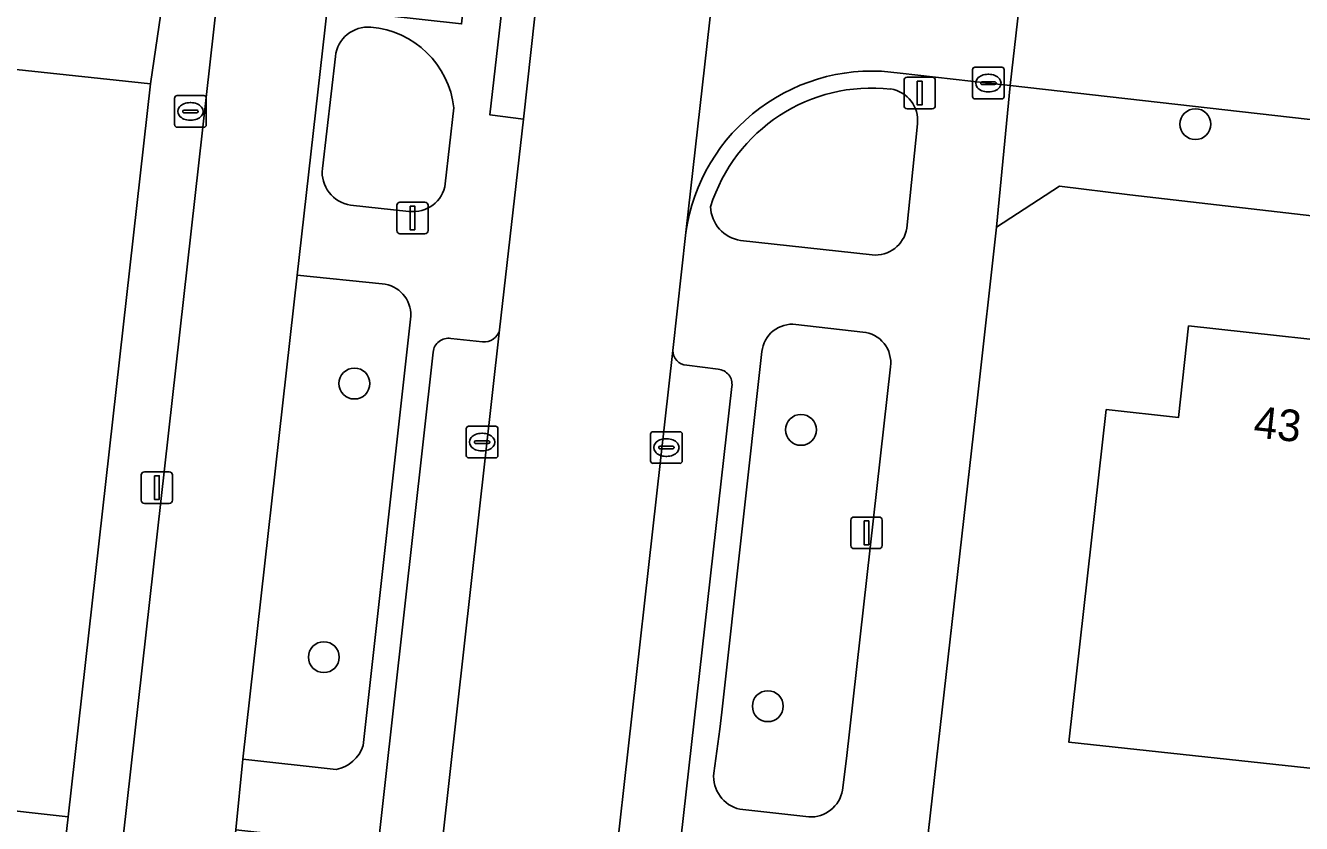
# Model space of a CAD drawing. Extents: x 162026 to 163502, y 387295 to 388169.
# Drawn here: x 162271.99 to 162312.4, y 387792.48 to 387817.74 of the extents above; entities that cross this region are included whole.
import ezdxf

# ---------------------------------------------------------------- set-up
doc = ezdxf.new("R2010")
doc.units = 0
for name, color, linetype in [('IMGEO_Berm_groen', 7, 'Continuous'), ('IMGEO_Boom', 7, 'Continuous'), ('IMGEO_Brandkraan', 7, 'Continuous'), ('IMGEO_Erf', 7, 'Continuous'), ('IMGEO_Fietspad_gesloten', 7, 'Continuous'), ('IMGEO_Groenvoorziening', 7, 'Continuous'), ('IMGEO_Kolk', 7, 'Continuous'), ('IMGEO_Lichtmast', 7, 'Continuous'), ('IMGEO_Muur', 7, 'Continuous'), ('IMGEO_Pand', 7, 'Continuous'), ('IMGEO_Pand_nummerreeks', 7, 'Continuous'), ('IMGEO_Parkeervlak_open', 7, 'Continuous'), ('IMGEO_Rijbaan_lokaal_gesloten', 7, 'Continuous'), ('IMGEO_Rijbaan_lokaal_open', 7, 'Continuous'), ('IMGEO_Voetpad_open', 7, 'Continuous')]:
    doc.layers.add(name, color=color, linetype=linetype)

msp = doc.modelspace()

# ---------------------------------------------------------------- linework, layer by layer
at = {"layer": 'IMGEO_Berm_groen'}
for points in [[(162283.29, 387809.569), (162280.59, 387809.842), (162278.879, 387794.52), (162281.83, 387794.192)], [(162282.682, 387794.949), (162284.192, 387808.546)]]:
    msp.add_lwpolyline(points, dxfattribs=at)
for centre, radius, start, end in [((162283.197, 387808.578), 0.995, 358.159, 84.6476), ((162281.627, 387795.278), 1.105, 280.573, 342.669)]:
    msp.add_arc(centre, radius, start, end, dxfattribs=at)
at = {"layer": 'IMGEO_Boom'}
for centre in [(162309.038, 387814.62), (162282.408, 387806.409), (162296.549, 387804.942), (162281.44, 387797.746), (162295.498, 387796.193)]:
    msp.add_circle(centre, 0.489, dxfattribs=at)
at = {"layer": 'IMGEO_Brandkraan'}
for p, q in [((162276.715, 387814.598), (162276.715, 387815.45)), ((162276.79, 387815.524), (162277.642, 387815.524)), ((162277.203, 387815.304), (162277.228, 387815.304)), ((162277.716, 387815.45), (162277.716, 387814.598)), ((162276.974, 387815.018), (162276.974, 387815.03)), ((162277.412, 387814.981), (162277.014, 387814.981)), ((162277.017, 387815.067), (162277.415, 387815.067)), ((162277.458, 387815.03), (162277.458, 387815.018)), ((162277.642, 387814.524), (162276.79, 387814.524)), ((162277.226, 387814.744), (162277.201, 387814.744))]:
    msp.add_line(p, q, dxfattribs=at)
for points in [[(162276.715, 387814.598), (162276.715, 387815.45)], [(162276.79, 387815.524), (162277.642, 387815.524)], [(162277.716, 387815.45), (162277.716, 387814.598)], [(162277.642, 387814.524), (162276.79, 387814.524)]]:
    msp.add_lwpolyline(points, dxfattribs=at)
for centre, radius, start, end in [((162276.792, 387815.448), 0.0765, 91.552, 178.448), ((162276.792, 387815.448), 0.0765, 91.552, 178.448), ((162277.64, 387815.448), 0.0765, 1.552, 88.448), ((162277.64, 387815.448), 0.0765, 1.552, 88.448), ((162277.014, 387815.027), 0.0403, 85.8775, 175.7526), ((162277.011, 387815.017), 0.0366, 178.938, 274.7102), ((162277.415, 387815.024), 0.043, 264.8664, 352.4533), ((162277.419, 387815.029), 0.0386, 1.7309, 96.639), ((162276.792, 387814.6), 0.0765, 181.552, 268.448), ((162276.792, 387814.6), 0.0765, 181.552, 268.448), ((162277.64, 387814.6), 0.0765, 271.552, 358.448), ((162277.64, 387814.6), 0.0765, 271.552, 358.448)]:
    msp.add_arc(centre, radius, start, end, dxfattribs=at)
for centre, major_axis, ratio, start_param, end_param in [((162277.202, 387815.024), (-0.387, 0.002), 0.722429, 4.712389, 7.853982), ((162277.227, 387815.024), (-0.39, 0.002), 0.717154, 1.570796, 4.712389)]:
    msp.add_ellipse(centre, major_axis=major_axis, ratio=ratio, start_param=start_param, end_param=end_param, dxfattribs=at)
at = {"layer": 'IMGEO_Erf'}
for points in [[(162275.948, 387815.9), (162270.899, 387816.432), (162239.75, 387819.947)], [(162230.846, 387799.89), (162235.219, 387799.415), (162234.953, 387796.965), (162242.578, 387796.117), (162273.341, 387792.696), (162275.948, 387815.9)], [(162360.929, 387806.153), (162306.963, 387812.388), (162304.731, 387812.656), (162302.745, 387811.357), (162302.135, 387805.96), (162300.281, 387789.552), (162306.672, 387788.828), (162307.029, 387791.981), (162313.859, 387791.208)], [(162314.036, 387794.079), (162305.036, 387795.05), (162306.214, 387805.585), (162308.506, 387805.337), (162308.825, 387808.234), (162315.35, 387807.516)]]:
    msp.add_lwpolyline(points, dxfattribs=at)
at = {"layer": 'IMGEO_Fietspad_gesloten'}
for points in [[(162288.097, 387908.488), (162278.956, 387826.545), (162278.87, 387825.665), (162278.372, 387825.72), (162277.589, 387818.699), (162278.067, 387818.669), (162270.183, 387748.502), (162261.381, 387669.505)], [(162272.106, 387733.912), (162275.454, 387763.658), (162275.701, 387765.902), (162278.652, 387792.276), (162278.879, 387794.52), (162280.59, 387809.842), (162281.546, 387818.246), (162282.058, 387818.211), (162282.843, 387825.189), (162282.325, 387825.242), (162283.687, 387837.34), (162286.582, 387863.057), (162286.832, 387865.282)]]:
    msp.add_lwpolyline(points, dxfattribs=at)
at = {"layer": 'IMGEO_Groenvoorziening'}
for points in [[(162281.805, 387816.766), (162281.392, 387813.219)], [(162285.286, 387812.735), (162285.557, 387815.137)], [(162299.898, 387811.328), (162300.234, 387814.631)], [(162282.288, 387812.06), (162284.135, 387811.861)], [(162294.631, 387810.939), (162298.798, 387810.481)], [(162298.505, 387808.039), (162296.389, 387808.281)], [(162295.313, 387807.419), (162294.044, 387796.005), (162293.984, 387795.465), (162293.785, 387794.073)], [(162297.868, 387793.536), (162297.989, 387794.536), (162299.382, 387806.943)], [(162294.612, 387792.931), (162296.796, 387792.686)]]:
    msp.add_lwpolyline(points, dxfattribs=at)
for centre, radius, start, end in [((162282.835, 387816.659), 1.035, 84.6226, 174.0724), ((162282.689, 387814.814), 2.886, 6.4231, 85.1702), ((162298.803, 387810.404), 5.362, 83.6997, 162.6313), ((162299.241, 387814.746), 1, 353.4127, 81.3672), ((162282.437, 387813.101), 1.051, 173.5496, 261.8642), ((162284.273, 387812.874), 1.023, 262.255, 352.1667), ((162294.802, 387812.043), 1.117, 181.9655, 261.2081), ((162298.903, 387811.483), 1.007, 264.0373, 351.1552), ((162296.276, 387807.32), 0.968, 83.2855, 174.112), ((162298.425, 387807.076), 0.966, 352.0641, 85.2682), ((162294.853, 387793.976), 1.072, 174.8111, 257.0107), ((162296.843, 387793.727), 1.042, 267.4004, 349.4221)]:
    msp.add_arc(centre, radius, start, end, dxfattribs=at)
at = {"layer": 'IMGEO_Kolk'}
for p, q in [((162301.982, 387815.495), (162301.982, 387816.347)), ((162302.057, 387816.421), (162302.909, 387816.421)), ((162302.47, 387816.201), (162302.495, 387816.201)), ((162302.983, 387816.347), (162302.983, 387815.495)), ((162302.241, 387815.915), (162302.241, 387815.927)), ((162302.679, 387815.878), (162302.281, 387815.878)), ((162302.284, 387815.964), (162302.682, 387815.964)), ((162302.493, 387815.641), (162302.468, 387815.641)), ((162302.725, 387815.927), (162302.725, 387815.915)), ((162302.909, 387815.421), (162302.057, 387815.421)), ((162285.95, 387804.129), (162285.95, 387804.981)), ((162286.025, 387805.055), (162286.877, 387805.055)), ((162286.438, 387804.835), (162286.463, 387804.835)), ((162286.951, 387804.981), (162286.951, 387804.129)), ((162291.786, 387803.957), (162291.786, 387804.809)), ((162291.861, 387804.883), (162292.713, 387804.883)), ((162292.787, 387804.809), (162292.787, 387803.957)), ((162286.209, 387804.549), (162286.209, 387804.561)), ((162286.647, 387804.512), (162286.249, 387804.512)), ((162286.252, 387804.598), (162286.65, 387804.598)), ((162286.693, 387804.561), (162286.693, 387804.549)), ((162292.045, 387804.377), (162292.045, 387804.389)), ((162292.483, 387804.34), (162292.085, 387804.34)), ((162292.088, 387804.426), (162292.486, 387804.426)), ((162292.274, 387804.663), (162292.299, 387804.663)), ((162292.529, 387804.389), (162292.529, 387804.377)), ((162286.877, 387804.055), (162286.025, 387804.055)), ((162286.461, 387804.275), (162286.436, 387804.275)), ((162292.297, 387804.103), (162292.272, 387804.103)), ((162292.713, 387803.883), (162291.861, 387803.883))]:
    msp.add_line(p, q, dxfattribs=at)
for points in [[(162301.982, 387815.495), (162301.982, 387816.347)], [(162302.057, 387816.421), (162302.909, 387816.421)], [(162302.983, 387816.347), (162302.983, 387815.495)], [(162302.909, 387815.421), (162302.057, 387815.421)], [(162285.95, 387804.129), (162285.95, 387804.981)], [(162286.025, 387805.055), (162286.877, 387805.055)], [(162286.951, 387804.981), (162286.951, 387804.129)], [(162291.786, 387803.957), (162291.786, 387804.809)], [(162291.861, 387804.883), (162292.713, 387804.883)], [(162292.787, 387804.809), (162292.787, 387803.957)], [(162286.877, 387804.055), (162286.025, 387804.055)], [(162292.713, 387803.883), (162291.861, 387803.883)]]:
    msp.add_lwpolyline(points, dxfattribs=at)
for centre, radius, start, end in [((162302.059, 387816.345), 0.0765, 91.552, 178.448), ((162302.059, 387816.345), 0.0765, 91.552, 178.448), ((162302.907, 387816.345), 0.0765, 1.552, 88.448), ((162302.907, 387816.345), 0.0765, 1.552, 88.448), ((162302.281, 387815.924), 0.0403, 85.8775, 175.7526), ((162302.278, 387815.914), 0.0366, 178.938, 274.7102), ((162302.682, 387815.921), 0.043, 264.8664, 352.4533), ((162302.686, 387815.926), 0.0386, 1.7309, 96.639), ((162302.059, 387815.497), 0.0765, 181.552, 268.448), ((162302.059, 387815.497), 0.0765, 181.552, 268.448), ((162302.907, 387815.497), 0.0765, 271.552, 358.448), ((162302.907, 387815.497), 0.0765, 271.552, 358.448), ((162286.027, 387804.979), 0.0765, 91.552, 178.448), ((162286.027, 387804.979), 0.0765, 91.552, 178.448), ((162286.875, 387804.979), 0.0765, 1.552, 88.448), ((162286.875, 387804.979), 0.0765, 1.552, 88.448), ((162291.863, 387804.807), 0.0765, 91.552, 178.448), ((162291.863, 387804.807), 0.0765, 91.552, 178.448), ((162292.711, 387804.807), 0.0765, 1.552, 88.448), ((162292.711, 387804.807), 0.0765, 1.552, 88.448), ((162286.249, 387804.558), 0.0403, 85.8775, 175.7526), ((162286.246, 387804.548), 0.0366, 178.938, 274.7102), ((162286.65, 387804.555), 0.043, 264.8664, 352.4533), ((162286.654, 387804.56), 0.0386, 1.7309, 96.639), ((162292.085, 387804.386), 0.0403, 85.8775, 175.7526), ((162292.082, 387804.376), 0.0366, 178.938, 274.7102), ((162292.486, 387804.383), 0.043, 264.8664, 352.4533), ((162292.49, 387804.388), 0.0386, 1.7309, 96.639), ((162286.027, 387804.131), 0.0765, 181.552, 268.448), ((162286.027, 387804.131), 0.0765, 181.552, 268.448), ((162286.875, 387804.131), 0.0765, 271.552, 358.448), ((162286.875, 387804.131), 0.0765, 271.552, 358.448), ((162291.863, 387803.959), 0.0765, 181.552, 268.448), ((162291.863, 387803.959), 0.0765, 181.552, 268.448), ((162292.711, 387803.959), 0.0765, 271.552, 358.448), ((162292.711, 387803.959), 0.0765, 271.552, 358.448)]:
    msp.add_arc(centre, radius, start, end, dxfattribs=at)
for centre, major_axis, ratio, start_param, end_param in [((162302.469, 387815.921), (-0.387, 0.002), 0.722429, 4.712389, 7.853982), ((162302.494, 387815.921), (-0.39, 0.002), 0.717154, 1.570796, 4.712389), ((162286.437, 387804.555), (-0.387, 0.002), 0.722429, 4.712389, 7.853982), ((162286.462, 387804.555), (-0.39, 0.002), 0.717154, 1.570796, 4.712389), ((162292.273, 387804.383), (-0.387, 0.002), 0.722429, 4.712389, 7.853982), ((162292.298, 387804.383), (-0.39, 0.002), 0.717154, 1.570796, 4.712389)]:
    msp.add_ellipse(centre, major_axis=major_axis, ratio=ratio, start_param=start_param, end_param=end_param, dxfattribs=at)
at = {"layer": 'IMGEO_Lichtmast'}
for p, q in [((162299.913, 387816.104), (162300.703, 387816.104)), ((162300.703, 387816.104), (162299.913, 387816.104)), ((162299.813, 387815.204), (162299.813, 387816.004)), ((162299.813, 387816.004), (162299.813, 387815.204)), ((162300.803, 387816.004), (162300.803, 387815.204)), ((162300.803, 387815.204), (162300.803, 387816.004)), ((162300.703, 387815.104), (162299.913, 387815.104)), ((162299.913, 387815.104), (162300.703, 387815.104)), ((162283.749, 387811.252), (162283.749, 387812.052)), ((162283.749, 387812.052), (162283.749, 387811.252)), ((162283.849, 387812.152), (162284.639, 387812.152)), ((162284.639, 387812.152), (162283.849, 387812.152)), ((162284.739, 387812.052), (162284.739, 387811.252)), ((162284.739, 387811.252), (162284.739, 387812.052)), ((162284.639, 387811.152), (162283.849, 387811.152)), ((162283.849, 387811.152), (162284.639, 387811.152)), ((162275.655, 387802.715), (162275.655, 387803.515)), ((162275.655, 387803.515), (162275.655, 387802.715)), ((162275.755, 387803.615), (162276.545, 387803.615)), ((162276.545, 387803.615), (162275.755, 387803.615)), ((162276.645, 387803.515), (162276.645, 387802.715)), ((162276.645, 387802.715), (162276.645, 387803.515)), ((162276.545, 387802.615), (162275.755, 387802.615)), ((162275.755, 387802.615), (162276.545, 387802.615)), ((162298.126, 387801.282), (162298.126, 387802.082)), ((162298.126, 387802.082), (162298.126, 387801.282)), ((162298.226, 387802.182), (162299.016, 387802.182)), ((162299.016, 387802.182), (162298.226, 387802.182)), ((162299.116, 387802.082), (162299.116, 387801.282)), ((162299.116, 387801.282), (162299.116, 387802.082)), ((162299.016, 387801.182), (162298.226, 387801.182)), ((162298.226, 387801.182), (162299.016, 387801.182))]:
    msp.add_line(p, q, dxfattribs=at)
for points in [[(162300.233, 387815.979), (162300.383, 387815.979), (162300.383, 387815.229), (162300.233, 387815.229), (162300.233, 387815.979)], [(162284.169, 387812.027), (162284.319, 387812.027), (162284.319, 387811.277), (162284.169, 387811.277), (162284.169, 387812.027)], [(162276.075, 387803.49), (162276.225, 387803.49), (162276.225, 387802.74), (162276.075, 387802.74), (162276.075, 387803.49)], [(162298.546, 387802.057), (162298.696, 387802.057), (162298.696, 387801.307), (162298.546, 387801.307), (162298.546, 387802.057)]]:
    msp.add_lwpolyline(points, dxfattribs=at)
for centre, start, end in [((162299.913, 387816.004), 90, 180), ((162299.913, 387816.004), 90, 180), ((162300.703, 387816.004), 0, 90), ((162300.703, 387816.004), 360, 90), ((162299.913, 387815.204), 180, 270), ((162299.913, 387815.204), 180, 270), ((162300.703, 387815.204), 270, 0), ((162300.703, 387815.204), 270, 0), ((162283.849, 387812.052), 90, 180), ((162283.849, 387812.052), 90, 180), ((162284.639, 387812.052), 0, 90), ((162284.639, 387812.052), 360, 90), ((162283.849, 387811.252), 180, 270), ((162283.849, 387811.252), 180, 270), ((162284.639, 387811.252), 270, 0), ((162284.639, 387811.252), 270, 0), ((162275.755, 387803.515), 90, 180), ((162275.755, 387803.515), 90, 180), ((162276.545, 387803.515), 0, 90), ((162276.545, 387803.515), 360, 90), ((162275.755, 387802.715), 180, 270), ((162275.755, 387802.715), 180, 270), ((162276.545, 387802.715), 270, 0), ((162276.545, 387802.715), 270, 0), ((162298.226, 387802.082), 90, 180), ((162298.226, 387802.082), 90, 180), ((162299.016, 387802.082), 0, 90), ((162299.016, 387802.082), 360, 90), ((162298.226, 387801.282), 180, 270), ((162298.226, 387801.282), 180, 270), ((162299.016, 387801.282), 270, 0), ((162299.016, 387801.282), 270, 0)]:
    msp.add_arc(centre, 0.1, start, end, dxfattribs=at)
at = {"layer": 'IMGEO_Muur'}
msp.add_lwpolyline([(162300.27, 387789.459), (162302.135, 387805.96)], dxfattribs=at)
at = {"layer": 'IMGEO_Pand'}
msp.add_lwpolyline([(162308.825, 387808.234), (162308.506, 387805.337), (162306.214, 387805.585), (162305.036, 387795.05), (162314.036, 387794.079), (162314.475, 387798.313), (162314.61, 387799.534), (162314.473, 387799.549), (162315.35, 387807.516)], close=True, dxfattribs=at)
at = {"layer": 'IMGEO_Parkeervlak_open'}
for points in [[(162280.695, 387751.699), (162287.006, 387808.114)], [(162286.46, 387807.73), (162285.462, 387807.834)], [(162284.902, 387807.407), (162278.703, 387751.857), (162273.411, 387704.935), (162275.389, 387704.712), (162277.051, 387719.431), (162280.695, 387751.699)], [(162292.493, 387807.458), (162285.406, 387744.3), (162281.03, 387705.382)], [(162293.929, 387806.859), (162292.929, 387806.99)], [(162283.154, 387706.135), (162287.384, 387743.942), (162292.495, 387789.737), (162292.997, 387794.228), (162294.36, 387806.319)]]:
    msp.add_lwpolyline(points, dxfattribs=at)
for centre, radius, start, end in [((162286.517, 387808.229), 0.502, 263.4722, 346.765), ((162285.374, 387807.369), 0.473, 79.2655, 175.3856), ((162292.954, 387807.45), 0.461, 179.04, 266.9053), ((162293.896, 387806.391), 0.469, 351.1919, 85.9983)]:
    msp.add_arc(centre, radius, start, end, dxfattribs=at)
at = {"layer": 'IMGEO_Rijbaan_lokaal_gesloten'}
for points in [[(162293.541, 387866.933), (162293.019, 387862.21), (162290.172, 387836.436), (162289.313, 387828.914), (162289.192, 387827.743), (162287.762, 387814.78), (162287.006, 387808.114), (162280.695, 387751.699), (162277.051, 387719.431)], [(162285.406, 387744.3), (162292.493, 387807.458), (162292.904, 387811.196), (162294.998, 387829.811), (162295.007, 387829.89), (162295.154, 387831.121), (162295.688, 387835.856), (162298.53, 387861.44), (162299.054, 387866.158)]]:
    msp.add_lwpolyline(points, dxfattribs=at)
at = {"layer": 'IMGEO_Rijbaan_lokaal_open'}
for points in [[(162294.998, 387829.811), (162292.904, 387811.196)], [(162299.685, 387816.236), (162302.483, 387815.921), (162303.178, 387815.842), (162303.964, 387822.804)], [(162395.53, 387807.317), (162392.118, 387808.232), (162387.179, 387809.517), (162381.46, 387811.044), (162377.782, 387812.01), (162373.697, 387813.078), (162367.97, 387814.57), (162363.334, 387815.705), (162362.667, 387815.86), (162355.672, 387817.005), (162351.81, 387817.477), (162310.236, 387822.094), (162305.011, 387822.692), (162303.964, 387822.804), (162303.178, 387815.842), (162315.741, 387814.416), (162356.078, 387809.716)]]:
    msp.add_lwpolyline(points, dxfattribs=at)
msp.add_arc((162298.797, 387810.349), 5.953, 81.4213, 171.8221, dxfattribs=at)
at = {"layer": 'IMGEO_Voetpad_open'}
for points in [[(162278.638, 387840.188), (162277.973, 387834.139), (162277.255, 387827.421), (162277.144, 387825.832), (162276.387, 387818.853), (162275.948, 387815.9), (162273.341, 387792.696), (162273.165, 387791.126), (162268.384, 387748.57), (162263.701, 387706.408), (162263.602, 387705.513), (162260.688, 387679.28), (162259.835, 387671.845), (162259.358, 387667.311)], [(162286.395, 387837.019), (162283.687, 387837.34), (162282.325, 387825.242), (162282.843, 387825.189), (162286.6, 387824.805), (162285.8, 387817.793), (162282.058, 387818.211), (162281.546, 387818.246), (162280.59, 387809.842), (162283.29, 387809.569)], [(162287.006, 387808.114), (162287.762, 387814.78), (162286.696, 387814.913), (162288.172, 387827.858), (162289.192, 387827.743), (162289.313, 387828.914), (162290.172, 387836.436)], [(162258.548, 387665.971), (162258.434, 387664.862), (162260.283, 387664.663), (162260.87, 387664.615), (162261.381, 387669.505), (162270.183, 387748.502), (162278.067, 387818.669), (162277.589, 387818.699), (162278.372, 387825.72)], [(162239.75, 387819.947), (162270.899, 387816.432), (162275.948, 387815.9), (162276.387, 387818.853), (162271.485, 387819.369), (162269.281, 387819.617), (162268.136, 387819.735), (162267.143, 387819.94), (162265.928, 387820.159), (162265.748, 387818.453), (162260.783, 387819.067), (162261.027, 387820.917), (162256.504, 387821.431), (162250.562, 387822.082), (162246.34, 387822.571), (162246.158, 387820.737), (162243.475, 387821.028), (162241.046, 387821.3), (162241.24, 387823.141)], [(162281.392, 387813.219), (162281.805, 387816.766)], [(162290.361, 387703.086), (162290.503, 387704.362), (162291.817, 387716.197), (162295.696, 387750.809), (162299.876, 387788.101), (162300.031, 387789.486), (162300.27, 387789.459), (162300.281, 387789.552), (162302.135, 387805.96), (162302.745, 387811.357), (162303.178, 387815.842), (162302.483, 387815.921), (162299.685, 387816.236)], [(162356.078, 387809.716), (162315.741, 387814.416), (162303.178, 387815.842), (162302.745, 387811.357), (162304.731, 387812.656), (162306.963, 387812.388), (162360.929, 387806.153), (162438.185, 387785.808), (162484.708, 387780.319)], [(162285.557, 387815.137), (162285.286, 387812.735)], [(162300.234, 387814.631), (162299.898, 387811.328)], [(162284.135, 387811.861), (162282.288, 387812.06)], [(162292.904, 387811.196), (162292.493, 387807.458)], [(162298.798, 387810.481), (162294.631, 387810.939)], [(162284.192, 387808.546), (162282.682, 387794.949)], [(162296.389, 387808.281), (162298.505, 387808.039)], [(162285.462, 387807.834), (162286.46, 387807.73)], [(162273.411, 387704.935), (162278.703, 387751.857), (162284.902, 387807.407)], [(162293.785, 387794.073), (162293.984, 387795.465), (162294.044, 387796.005), (162295.313, 387807.419)], [(162292.929, 387806.99), (162293.929, 387806.859)], [(162299.382, 387806.943), (162297.989, 387794.536), (162297.868, 387793.536)], [(162294.36, 387806.319), (162292.997, 387794.228), (162292.495, 387789.737), (162287.384, 387743.942), (162283.154, 387706.135)], [(162281.83, 387794.192), (162278.879, 387794.52), (162278.652, 387792.276), (162281.616, 387791.948)], [(162296.796, 387792.686), (162294.612, 387792.931)]]:
    msp.add_lwpolyline(points, dxfattribs=at)
for points in [[(162289.192, 387827.743), (162288.172, 387827.858), (162286.696, 387814.913), (162287.762, 387814.78)], [(162242.578, 387796.117), (162242.378, 387794.629), (162247.348, 387794.074), (162248.361, 387793.961), (162258.402, 387792.758), (162262.22, 387792.336), (162267.189, 387791.787), (162273.165, 387791.126), (162273.341, 387792.696)]]:
    msp.add_lwpolyline(points, close=True, dxfattribs=at)
for centre, radius, start, end in [((162282.835, 387816.659), 1.035, 84.6226, 174.0724), ((162282.689, 387814.814), 2.886, 6.4231, 85.1702), ((162298.797, 387810.349), 5.953, 81.4213, 171.8221), ((162298.803, 387810.404), 5.362, 83.6997, 162.6313), ((162299.241, 387814.746), 1, 353.4127, 81.3672), ((162282.437, 387813.101), 1.051, 173.5496, 261.8642), ((162284.273, 387812.874), 1.023, 262.255, 352.1667), ((162294.802, 387812.043), 1.117, 181.9655, 261.2081), ((162298.903, 387811.483), 1.007, 264.0373, 351.1552), ((162283.197, 387808.578), 0.995, 358.159, 84.6476), ((162286.517, 387808.229), 0.502, 263.4722, 346.765), ((162296.276, 387807.32), 0.968, 83.2855, 174.112), ((162298.425, 387807.076), 0.966, 352.0641, 85.2682), ((162285.374, 387807.369), 0.473, 79.2655, 175.3856), ((162292.954, 387807.45), 0.461, 179.04, 266.9053), ((162293.896, 387806.391), 0.469, 351.1919, 85.9983), ((162281.627, 387795.278), 1.105, 280.573, 342.669), ((162294.853, 387793.976), 1.072, 174.8111, 257.0107), ((162296.843, 387793.727), 1.042, 267.4004, 349.4221)]:
    msp.add_arc(centre, radius, start, end, dxfattribs=at)

# ---------------------------------------------------------------- texts
at = {"layer": 'IMGEO_Pand_nummerreeks'}
msp.add_text('43', height=1, rotation=353.7219, dxfattribs=at).set_placement((162310.852, 387804.711))

doc.saveas('drawing.dxf')
